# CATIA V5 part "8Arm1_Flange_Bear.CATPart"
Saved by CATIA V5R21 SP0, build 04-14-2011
Part number: Arm1_Flange_Bear
Bounding box of the stored display mesh (mm): x -11.5 to 11.5, y -11.5 to 11.5, z 0 to 5
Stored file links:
  F:\教程\Robotic_Arm_Arduino_Kinect\机械臂CAD\arm\Arm1_Flange_Bear.CATPart
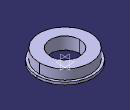
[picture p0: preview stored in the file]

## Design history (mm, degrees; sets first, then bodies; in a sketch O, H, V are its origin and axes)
Body1 (main body)
  Sketch1 on xy-plane, origin (0, 0, 0), H (1, 0, 0), V (0, 1, 0)
    circle A1 centre (0, 0) radius 11.5
    radius A1 = 11.5
  Pad1: profile Sketch1, direction (0, 0, 1), length 1
  Sketch2 on end face of Pad1, origin (0, 0, 1), H (1, 0, 0), V (0, 1, 0)
    circle A1 centre (0, 0) radius 10.5
    radius A1 = 10.5
  Pad2: profile Sketch2, direction (0, 0, 1), length 4
  Sketch3 on end face of Pad2, origin (0, 0, 5), H (1, 0, 0), V (0, 1, 0)
    circle A1 centre (0, 0) radius 6
    radius A1 = 6
  Pocket1: profile Sketch3, direction (0, 0, -1), through (limit type 3)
